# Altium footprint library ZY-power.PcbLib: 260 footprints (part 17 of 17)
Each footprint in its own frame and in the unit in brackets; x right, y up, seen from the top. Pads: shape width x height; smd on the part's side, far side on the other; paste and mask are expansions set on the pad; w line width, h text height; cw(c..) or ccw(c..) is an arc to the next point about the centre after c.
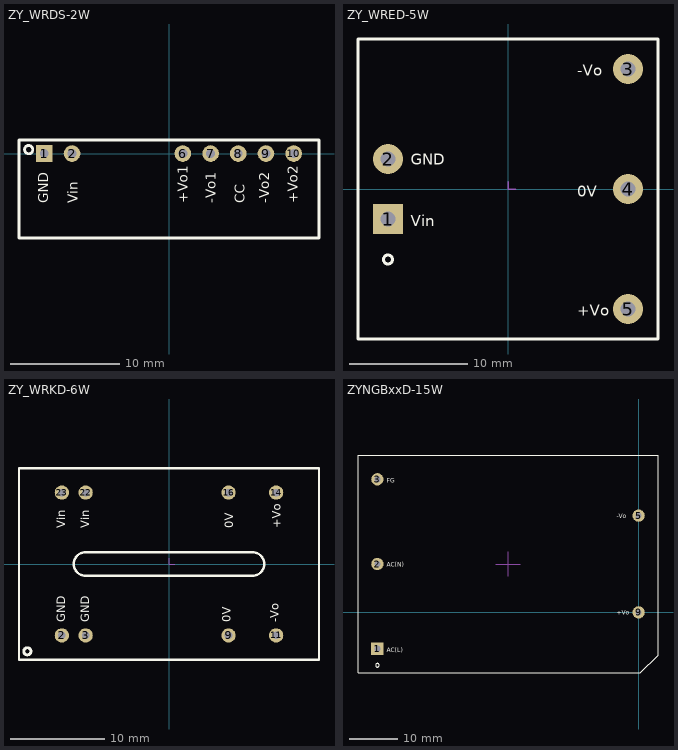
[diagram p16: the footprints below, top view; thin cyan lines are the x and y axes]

## ZY_WRDS-2W [mil]
height 452.76
pads (7):
  rect 60x60 hole 32: 1(-450,0)
  round 60 hole 32: 2(-350,0) 6(50,0) 7(150,0) 8(250,0) 9(350,0) 10(450,0)
Top Overlay:
  circle w10: c-506.34,14.21 r15
  lines w10: -541.34,-305.12 541.34,-305.12 541.34,49.21 -541.34,49.21 -541.34,-305.12
  text "-Vo1" at 168,-180 h36
  text "+Vo1" at 67,-180 h36
  text "Vin" at -330,-180 h36
  text "GND" at -435,-180 h36
  text "CC" at 274,-180 h36
  text "+Vo2" at 465,-180 h36
  text "-Vo2" at 362,-180 h36

## ZY_WRED-5W [mil]
height 460.63
pads (5):
  rect 100x100 hole 50: 1(-400,-100)
  round 100 hole 50: 2(-400,100) 3(400,400) 4(400,0) 5(400,-400)
Top Overlay:
  circle w10: c-400,-235 r15
  lines w10: -500,-500 500,-500 500,500 -500,500 -500,-500
  text "0V" at 230,-25 h36
  text "GND" at -325,81 h36
  text "Vin" at -325,-124 h36
  text "+Vo" at 230,-423 h36
  text "-Vo" at 230,377 h36
Mechanical 15:
  lines w5: 0,25 0,0 25,0

## ZY_WRKD-6W [mil]
height 413.39
pads (8):
  round 60 hole 32: 2(-450,-300) 3(-350,-300) 9(250,-300) 11(450,-300) 14(450,300) 16(250,300) 22(-350,300) 23(-450,300)
Top Overlay:
  circle w12: c-594.92,-366.57 r15
  lines w10: -629.92,-401.57 -629.92,401.57 629.92,401.57 629.92,-401.57 -629.92,-401.57 ; -400,0 ccw(c-350,0) -350,-50 350,-50 ccw(c350,0) 400,0 ccw(c350,0) 350,50 -350,50 ccw(c-350,0) -400,0
  text "0V" at 260,-245 h36
  text "GND" at -435,-245 h36
  text "GND" at -335,-245 h36
  text "Vin" at -435,150 h36
  text "Vin" at -335,150 h36
  text "-Vo" at 460,-245 h36
  text "+Vo" at 470,150 h36
  text "0V" at 270,150 h36
Mechanical 15:
  lines w5: 0,25 0,0 25,0

## ZYNGBxxD-15W [mm] "120426 修改 by kong"
height 22.5
pads (5):
  rect 2.54x2.54 hole 1.27: 1(-54,-7.5)
  round 2.54 hole 1.27: 2(-54,10) 3(-54,27.5) 5(0,20) 9(0,0)
Top Overlay:
  circle w0.254: c-54,-10.929 r0.381
  lines w0.254: -58,-12.5 0.325,-12.5 4,-8.825 4,32.5 -58,32.5 -58,-12.5
  text "AC(L)" at -52.095,-8.262 h0.91
  text "AC(N)" at -52.095,9.391 h0.91
  text "FG" at -52.095,26.79 h0.91
  text "+Vo" at -4.572,-0.515 h0.91
  text "-Vo" at -4.572,19.424 h0.91
Mechanical 15:
  lines w0.152: -29.54,10 -24.46,10 ; -27,7.46 -27,12.54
